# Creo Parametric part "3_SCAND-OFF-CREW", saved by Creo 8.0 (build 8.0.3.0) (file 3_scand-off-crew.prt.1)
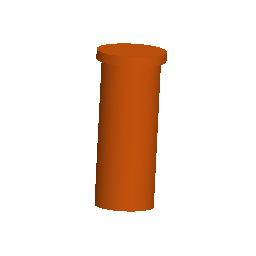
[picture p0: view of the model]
Units: millimeter Newton Second (mmNs); MM, TONNE, SECS

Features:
  1. protrusion
  2. datum plane "DTM3"
  3. protrusion
  4. datum plane "DTM1"
  5. datum plane "DTM2"

Layers: 0_ALL_AXIS, 0_ALL_CSYS, 0_ALL_CURVES, 0_ALL_PLANES, 0_ALL_POINTS, 0_ALL_SURFS, SCAND-OFF-CREW

Surfaces: 3 plane, 2 cylinder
